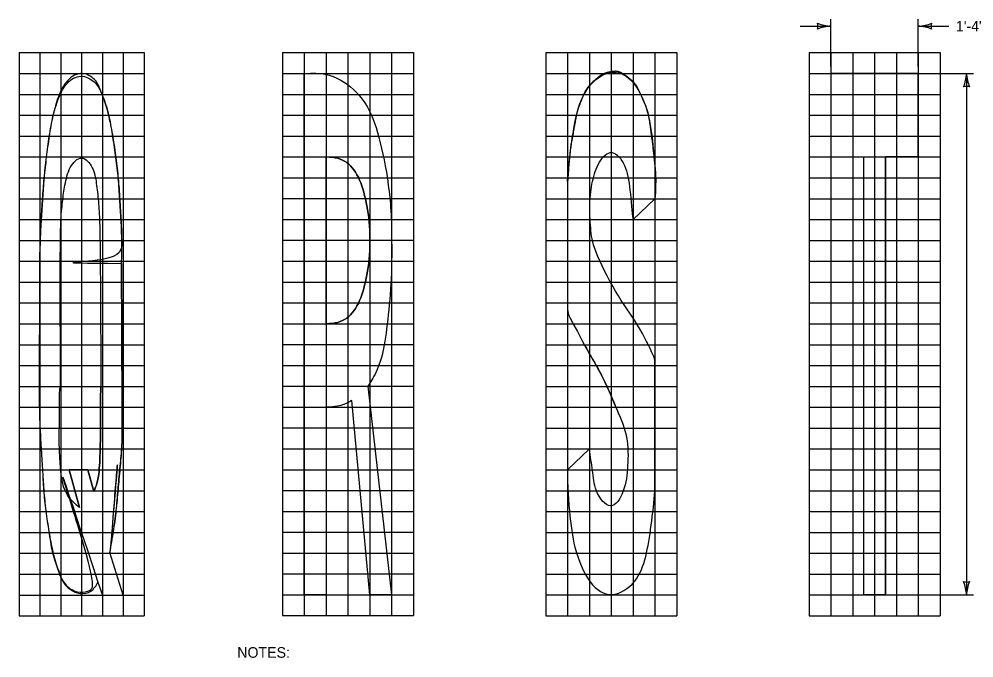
# Model space of a CAD drawing. Extents: x 49991.4 to 50021, y 49987.6 to 50011.4.
# Drawn here: x 50007.25 to 50012.67, y 49991.57 to 49995.18 of the extents above; entities that cross this region are included whole.
import ezdxf

# ---------------------------------------------------------------- set-up
doc = ezdxf.new("R2010")
doc.units = 0
for name, color, linetype in [('Level 1', 7, 'Continuous'), ('Level 2', 7, 'Continuous'), ('Level 3', 7, 'Continuous'), ('Level 9', 7, 'Continuous')]:
    doc.layers.add(name, color=color, linetype=linetype)

msp = doc.modelspace()

# ---------------------------------------------------------------- linework, layer by layer
at = {"layer": 'Level 1'}
for p, q in [((50008.8704, 49991.9224), (50008.8704, 49994.8747)), ((50008.8704, 49991.9224), (50008.8704, 49994.8747)), ((50008.8704, 49991.9224), (50008.8704, 49994.8747)), ((50011.8554, 49994.8747), (50011.8554, 49994.4022)), ((50011.8554, 49994.8747), (50012.3504, 49994.8747)), ((50012.3504, 49994.8747), (50011.8554, 49994.8747)), ((50011.8554, 49994.8747), (50011.8554, 49994.4022)), ((50012.3504, 49994.8747), (50011.8554, 49994.8747)), ((50011.8554, 49994.8747), (50011.8554, 49994.4022)), ((50012.3504, 49994.8747), (50012.3504, 49994.4022)), ((50012.3504, 49994.4022), (50012.3504, 49994.8747)), ((50012.3504, 49994.4022), (50012.3504, 49994.8747)), ((50008.9941, 49993.4576), (50008.9941, 49994.4023)), ((50008.9941, 49994.4023), (50008.9941, 49993.4576)), ((50008.9941, 49994.4023), (50008.9941, 49993.4576)), ((50011.8554, 49994.4022), (50012.041, 49994.4022)), ((50011.8554, 49994.4022), (50012.041, 49994.4022)), ((50011.8554, 49994.4022), (50012.041, 49994.4022)), ((50012.041, 49994.4022), (50012.041, 49991.9215)), ((50012.041, 49994.4022), (50012.041, 49991.9215)), ((50012.041, 49994.4022), (50012.041, 49991.9215)), ((50012.3504, 49994.4022), (50012.1647, 49994.4022)), ((50012.1647, 49994.4022), (50012.1647, 49991.9215)), ((50012.1647, 49991.9215), (50012.1647, 49994.4022)), ((50012.1647, 49994.4022), (50012.3504, 49994.4022)), ((50012.1647, 49991.9215), (50012.1647, 49994.4022)), ((50012.1647, 49994.4022), (50012.3504, 49994.4022)), ((50010.3629, 49994.2641), (50010.3629, 49993.5406)), ((50010.3629, 49994.2641), (50010.3629, 49993.5406)), ((50010.8579, 49994.1659), (50010.7341, 49994.0478)), ((50010.7341, 49994.0478), (50010.8579, 49994.1659)), ((50007.3703, 49992.989), (50007.3716, 49993.8046)), ((50007.835, 49993.7992), (50007.839, 49992.9903)), ((50007.4881, 49993.1994), (50007.4862, 49993.6824)), ((50007.715, 49993.6894), (50007.7173, 49993.1045)), ((50010.8579, 49992.5122), (50010.8579, 49993.2364)), ((50010.8579, 49992.5122), (50010.8579, 49993.2364)), ((50007.4885, 49993.1091), (50007.4881, 49993.1994)), ((50009.23, 49993.1033), (50009.3654, 49991.9224)), ((50009.23, 49993.1033), (50009.3654, 49991.9224)), ((50009.23, 49993.1033), (50009.3654, 49991.9224)), ((50009.2416, 49991.9224), (50009.1397, 49993.0224)), ((50009.2416, 49991.9224), (50009.1397, 49993.0224)), ((50009.2416, 49991.9224), (50009.1397, 49993.0224)), ((50008.9941, 49992.9853), (50008.9941, 49991.9224)), ((50008.9941, 49992.9853), (50008.9941, 49991.9224)), ((50008.9941, 49992.9853), (50008.9941, 49991.9224)), ((50010.3629, 49992.6303), (50010.4866, 49992.7484)), ((50010.4866, 49992.7484), (50010.3629, 49992.6303)), ((50007.537, 49992.6306), (50007.6446, 49992.6306)), ((50007.5969, 49992.4179), (50007.537, 49992.6306)), ((50007.6446, 49992.6306), (50007.678, 49992.5081)), ((50007.8447, 49991.9214), (50007.7693, 49992.1614)), ((50007.701, 49991.994), (50007.7266, 49991.9214)), ((50007.7266, 49991.9214), (50007.8447, 49991.9214)), ((50008.9941, 49991.9224), (50008.8704, 49991.9224)), ((50008.9941, 49991.9224), (50008.8704, 49991.9224)), ((50008.9941, 49991.9224), (50008.8704, 49991.9224)), ((50009.3654, 49991.9224), (50009.2416, 49991.9224)), ((50009.3654, 49991.9224), (50009.2416, 49991.9224)), ((50009.3654, 49991.9224), (50009.2416, 49991.9224)), ((50012.1647, 49991.9215), (50012.041, 49991.9215)), ((50012.041, 49991.9215), (50012.1647, 49991.9215)), ((50012.041, 49991.9215), (50012.1647, 49991.9215))]:
    msp.add_line(p, q, dxfattribs=at)
for points in [[(50007.3716, 49993.8046), (50007.3703, 49992.989)], [(50007.839, 49992.9903), (50007.835, 49993.7992)], [(50007.4885, 49993.1091), (50007.4881, 49993.1994), (50007.4862, 49993.6824)], [(50007.715, 49993.6894), (50007.7173, 49993.1045)], [(50007.537, 49992.6306), (50007.5969, 49992.4179)], [(50007.678, 49992.5081), (50007.6446, 49992.6306), (50007.537, 49992.6306)], [(50007.8447, 49991.9214), (50007.7693, 49992.1614)], [(50007.701, 49991.994), (50007.7266, 49991.9214), (50007.8447, 49991.9214)]]:
    msp.add_lwpolyline(points, dxfattribs=at)
for centre, start, end in [((50010.4629, 49993.5406), 180, 208.2065), ((50010.4629, 49993.5406), 180, 208.2065), ((50010.7579, 49993.2364), 360, 27.9161), ((50010.7579, 49993.2364), 0.0009, 27.9162)]:
    msp.add_arc(centre, 0.1, start, end, dxfattribs=at)
for points, degree in [([(50007.835, 49993.7992), (50007.8358, 49993.8389), (50007.8372, 49993.9113), (50007.8338, 49994.0287), (50007.8259, 49994.1447), (50007.8184, 49994.2663), (50007.806, 49994.3829), (50007.7884, 49994.4994), (50007.7697, 49994.6188), (50007.7456, 49994.7072), (50007.7154, 49994.7773), (50007.6941, 49994.8419), (50007.6016, 49994.895), (50007.5124, 49994.8288), (50007.4698, 49994.7331), (50007.4408, 49994.6226), (50007.4219, 49994.5044), (50007.4058, 49994.386), (50007.3937, 49994.2685), (50007.3865, 49994.1518), (50007.3778, 49994.0363), (50007.3721, 49993.9202), (50007.3718, 49993.843), (50007.3716, 49993.8046)], 3), ([(50007.3716, 49993.8046), (50007.3729, 49993.9197), (50007.3783, 49994.0362), (50007.3863, 49994.1528), (50007.3944, 49994.2666), (50007.4064, 49994.3858), (50007.4225, 49994.505), (50007.4426, 49994.6215), (50007.4747, 49994.738), (50007.5229, 49994.8277), (50007.6019, 49994.8746), (50007.689, 49994.8304), (50007.7211, 49994.7648), (50007.7332, 49994.7353), (50007.768, 49994.6161), (50007.7881, 49994.5009), (50007.8055, 49994.3804), (50007.8175, 49994.2666), (50007.8256, 49994.1514), (50007.8336, 49994.0162), (50007.8363, 49993.9184), (50007.835, 49993.7992), (50007.3716, 49993.8046), (50007.835, 49993.7992)], 3), ([(50008.8704, 49994.8747), (50008.9676, 49994.8817), (50009.0761, 49994.8552), (50009.2272, 49994.718), (50009.2957, 49994.5267), (50009.3522, 49994.2481), (50009.3667, 49994.0494), (50009.3654, 49993.93)], 3), ([(50008.8704, 49994.8747), (50008.9676, 49994.8817), (50009.0761, 49994.8552), (50009.2272, 49994.718), (50009.2957, 49994.5267), (50009.3522, 49994.2481), (50009.3667, 49994.0494), (50009.3654, 49993.93)], 3), ([(50008.8704, 49994.8747), (50008.9676, 49994.8817), (50009.0761, 49994.8552), (50009.2272, 49994.718), (50009.2957, 49994.5267), (50009.3522, 49994.2481), (50009.3667, 49994.0494), (50009.3654, 49993.93)], 3), ([(50010.3629, 49994.2641), (50010.3736, 49994.419), (50010.4054, 49994.6066), (50010.4242, 49994.6921), (50010.4854, 49994.8224), (50010.61, 49994.9017), (50010.7256, 49994.8563), (50010.8047, 49994.7111), (50010.8404, 49994.5666), (50010.8682, 49994.2519), (50010.8579, 49994.1659)], 3), ([(50010.5214, 49994.8404), (50010.4744, 49994.7991), (50010.4494, 49994.7457), (50010.4341, 49994.7068)], 2), ([(50010.5916, 49994.8807), (50010.5668, 49994.8742), (50010.542, 49994.8585), (50010.5214, 49994.8404)], 2), ([(50010.7096, 49994.8497), (50010.678, 49994.875), (50010.6348, 49994.8919), (50010.5916, 49994.8807)], 2), ([(50010.7812, 49994.7485), (50010.7651, 49994.7839), (50010.7444, 49994.8218), (50010.7096, 49994.8497)], 2), ([(50010.8412, 49994.5093), (50010.8268, 49994.6217), (50010.8123, 49994.6805), (50010.7812, 49994.7485)], 2), ([(50010.4341, 49994.7068), (50010.4188, 49994.6677), (50010.4134, 49994.6431), (50010.405, 49994.5981)], 2), ([(50010.405, 49994.5981), (50010.3926, 49994.5312), (50010.3736, 49994.419), (50010.3629, 49994.2641)], 2), ([(50010.8579, 49994.1659), (50010.8682, 49994.2519), (50010.8547, 49994.404), (50010.8412, 49994.5093)], 2), ([(50008.9941, 49994.4023), (50009.0438, 49994.4022), (50009.1175, 49994.3823), (50009.1897, 49994.2795), (50009.2279, 49994.1296), (50009.2436, 49994.0108), (50009.2416, 49993.93)], 3), ([(50009.2416, 49993.93), (50009.2436, 49994.0108), (50009.2279, 49994.1296), (50009.1897, 49994.2795), (50009.1175, 49994.3823), (50009.0438, 49994.4022), (50008.9941, 49994.4023)], 3), ([(50009.2416, 49993.93), (50009.2436, 49994.0108), (50009.2279, 49994.1296), (50009.1897, 49994.2795), (50009.1175, 49994.3823), (50009.0438, 49994.4022), (50008.9941, 49994.4023)], 3), ([(50010.8462, 49993.2832), (50010.83, 49993.3224), (50010.7652, 49993.452), (50010.6343, 49993.6279), (50010.5054, 49993.8898), (50010.4936, 49993.991), (50010.4851, 49994.1427), (50010.5006, 49994.2637), (50010.5359, 49994.3783), (50010.6146, 49994.4552), (50010.6946, 49994.3608), (50010.7181, 49994.2259), (50010.7272, 49994.0852), (50010.7341, 49994.0478)], 3), ([(50010.8462, 49993.2832), (50010.83, 49993.3224), (50010.7652, 49993.452), (50010.6343, 49993.6279), (50010.5054, 49993.8898), (50010.4936, 49993.991), (50010.4851, 49994.1427), (50010.5006, 49994.2637), (50010.5359, 49994.3783), (50010.6146, 49994.4552), (50010.6946, 49994.3608), (50010.7181, 49994.2259), (50010.7272, 49994.0852), (50010.7341, 49994.0478)], 3), ([(50007.4862, 49993.6824), (50007.4862, 49993.7818), (50007.4885, 49993.8651), (50007.4885, 49994.0361), (50007.5002, 49994.1539), (50007.5116, 49994.2395), (50007.5364, 49994.3477), (50007.6091, 49994.4216), (50007.6771, 49994.3429), (50007.6923, 49994.2548), (50007.7043, 49994.1516), (50007.7114, 49994.0363), (50007.7131, 49993.8827), (50007.7143, 49993.7664), (50007.715, 49993.6894)], 3), ([(50007.4862, 49993.6824), (50007.4862, 49993.7818), (50007.4885, 49993.8651), (50007.4885, 49994.0361), (50007.5002, 49994.1539), (50007.5116, 49994.2395), (50007.5364, 49994.3477), (50007.6091, 49994.4216), (50007.6771, 49994.3429), (50007.6923, 49994.2548), (50007.7043, 49994.1516), (50007.7114, 49994.0363), (50007.7131, 49993.8827), (50007.7143, 49993.7664), (50007.715, 49993.6894)], 3), ([(50009.2416, 49993.93), (50009.2436, 49993.8491), (50009.2279, 49993.7304), (50009.1897, 49993.5805), (50009.1175, 49993.4777), (50009.0438, 49993.4578), (50008.9941, 49993.4576)], 3), ([(50008.9941, 49993.4576), (50009.0438, 49993.4578), (50009.1175, 49993.4777), (50009.1897, 49993.5805), (50009.2279, 49993.7304), (50009.2436, 49993.8491), (50009.2416, 49993.93)], 3), ([(50008.9941, 49993.4576), (50009.0438, 49993.4578), (50009.1175, 49993.4777), (50009.1897, 49993.5805), (50009.2279, 49993.7304), (50009.2436, 49993.8491), (50009.2416, 49993.93)], 3), ([(50009.3654, 49993.93), (50009.3674, 49993.8115), (50009.3618, 49993.6537), (50009.3371, 49993.4171), (50009.3111, 49993.2532), (50009.257, 49993.139), (50009.23, 49993.1033), (50009.23, 49993.1033)], 3), ([(50009.3654, 49993.93), (50009.3674, 49993.8115), (50009.3618, 49993.6537), (50009.3371, 49993.4171), (50009.3111, 49993.2532), (50009.257, 49993.139), (50009.23, 49993.1033), (50009.23, 49993.1033)], 3), ([(50009.3654, 49993.93), (50009.3674, 49993.8115), (50009.3618, 49993.6537), (50009.3371, 49993.4171), (50009.3111, 49993.2532), (50009.257, 49993.139), (50009.23, 49993.1033), (50009.23, 49993.1033)], 3), ([(50010.3747, 49993.4933), (50010.4442, 49993.3649), (50010.4819, 49993.2929), (50010.5713, 49993.1446), (50010.6455, 49992.9612), (50010.7081, 49992.8199), (50010.7054, 49992.6479), (50010.6897, 49992.509), (50010.6082, 49992.3829), (50010.5102, 49992.5148), (50010.5082, 49992.6247), (50010.4914, 49992.7076), (50010.4866, 49992.7484)], 3), ([(50010.3747, 49993.4933), (50010.4442, 49993.3649), (50010.4819, 49993.2929), (50010.5358, 49993.2034), (50010.5624, 49993.1506)], 3), ([(50007.5969, 49992.4179), (50007.579, 49992.4306), (50007.5041, 49992.4879), (50007.4869, 49992.6526), (50007.4833, 49992.732), (50007.4797, 49992.8331), (50007.4869, 49992.9667), (50007.4797, 49993.039), (50007.4885, 49993.1091)], 3), ([(50007.5969, 49992.4179), (50007.579, 49992.4306), (50007.5041, 49992.4879), (50007.4869, 49992.6526), (50007.4833, 49992.732), (50007.4797, 49992.8331), (50007.4869, 49992.9667), (50007.4797, 49993.039), (50007.4885, 49993.1091)], 3), ([(50007.678, 49992.5081), (50007.6929, 49992.5426), (50007.7081, 49992.5913), (50007.7145, 49992.7506), (50007.7153, 49992.8672), (50007.7144, 49992.9851), (50007.7163, 49993.0645), (50007.7173, 49993.1045)], 3), ([(50007.7173, 49993.1045), (50007.7163, 49993.0645), (50007.7144, 49992.9851), (50007.7153, 49992.8672), (50007.7145, 49992.7506), (50007.7081, 49992.5913), (50007.6929, 49992.5426), (50007.678, 49992.5081)], 3), ([(50010.5624, 49993.1506), (50010.5956, 49993.0845), (50010.6455, 49992.9612), (50010.7081, 49992.8199), (50010.7054, 49992.6479), (50010.6897, 49992.509), (50010.6082, 49992.3829), (50010.5102, 49992.5148), (50010.5082, 49992.6247), (50010.4914, 49992.7076), (50010.4866, 49992.7484)], 3), ([(50009.1397, 49993.0224), (50009.1397, 49993.0224), (50009.0969, 49992.9976), (50009.0488, 49992.986), (50008.9941, 49992.9853)], 3), ([(50009.1397, 49993.0224), (50009.1397, 49993.0224), (50009.0969, 49992.9976), (50009.0488, 49992.986), (50008.9941, 49992.9853)], 3), ([(50009.1397, 49993.0224), (50009.1397, 49993.0224), (50009.0969, 49992.9976), (50009.0488, 49992.986), (50008.9941, 49992.9853)], 3), ([(50007.3703, 49992.989), (50007.3716, 49992.8725), (50007.3783, 49992.7546), (50007.3863, 49992.6354), (50007.393, 49992.5176), (50007.4051, 49992.3957), (50007.4225, 49992.2819), (50007.4439, 49992.1614), (50007.4774, 49992.0542), (50007.5055, 49991.9913), (50007.5403, 49991.9551), (50007.5993, 49991.931), (50007.6609, 49991.9431), (50007.701, 49991.994), (50007.3703, 49992.989), (50007.701, 49991.994)], 3), ([(50007.3703, 49992.989), (50007.3703, 49992.9501), (50007.3703, 49992.8719), (50007.3782, 49992.7541), (50007.3869, 49992.6359), (50007.3921, 49992.5161), (50007.4033, 49992.3979), (50007.4235, 49992.2797), (50007.4394, 49992.1636), (50007.4724, 49992.0682), (50007.4984, 49991.9943), (50007.5419, 49991.9495), (50007.5972, 49991.9249), (50007.6676, 49991.9355), (50007.6898, 49991.9743), (50007.701, 49991.994)], 3), ([(50007.839, 49992.9903), (50007.839, 49992.8738), (50007.8363, 49992.7533), (50007.8256, 49992.6368), (50007.8149, 49992.5189), (50007.8042, 49992.3984), (50007.7881, 49992.2806), (50007.7693, 49992.1614), (50007.839, 49992.9903), (50007.7693, 49992.1614)], 3), ([(50007.7693, 49992.1614), (50007.7757, 49992.2011), (50007.7883, 49992.2799), (50007.8056, 49992.3989), (50007.8145, 49992.5181), (50007.8251, 49992.6364), (50007.8385, 49992.7543), (50007.8391, 49992.8725), (50007.839, 49992.9515), (50007.839, 49992.9903)], 3), ([(50010.3629, 49992.6303), (50010.3601, 49992.5469), (50010.3758, 49992.3477), (50010.4017, 49992.1716), (50010.484, 49991.9767), (50010.6105, 49991.8938), (50010.7572, 49991.9905), (50010.8096, 49992.1339), (50010.8372, 49992.3119), (50010.8536, 49992.4514), (50010.8579, 49992.5122)], 3), ([(50010.3629, 49992.6303), (50010.3601, 49992.5469), (50010.3758, 49992.3477), (50010.4017, 49992.1716), (50010.484, 49991.9767), (50010.6105, 49991.8938), (50010.7572, 49991.9905), (50010.8096, 49992.1339), (50010.8372, 49992.3119), (50010.8536, 49992.4514), (50010.8579, 49992.5122)], 3)]:
    msp.add_open_spline(points, degree=degree, dxfattribs=at)
at = {"layer": 'Level 3'}
for p, q in [((50011.8554, 49994.9147), (50011.8554, 49995.1828)), ((50012.3504, 49994.9147), (50012.3504, 49995.1828)), ((50011.682, 49995.1428), (50011.8554, 49995.1428)), ((50012.3504, 49995.1428), (50012.5238, 49995.1428)), ((50012.3904, 49994.8747), (50012.6641, 49994.8747)), ((50012.6241, 49994.8747), (50012.6241, 49991.9215)), ((50012.2047, 49991.9215), (50012.6641, 49991.9215))]:
    msp.add_line(p, q, dxfattribs=at)
for centre, radius, start, end in [((50011.8645, 49995.3649), 0.2223, 247.456, 267.6395), ((50011.7271, 49995.1428), 0.0548, 342.1388, 17.8612), ((50011.8669, 49994.9101), 0.233, 92.8273, 112.0772), ((50012.3389, 49995.3755), 0.233, 272.8273, 292.0772), ((50012.3412, 49994.9207), 0.2223, 67.456, 87.6395), ((50012.4786, 49995.1428), 0.0548, 162.1388, 197.8612), ((50012.402, 49994.8838), 0.2223, 337.456, 357.6395), ((50012.8568, 49994.8862), 0.233, 182.8273, 202.0772), ((50012.6241, 49994.7465), 0.0548, 72.1388, 107.8612), ((50012.6241, 49992.0498), 0.0548, 252.1388, 287.8612), ((50012.3914, 49991.91), 0.233, 2.8273, 22.0772), ((50012.8462, 49991.9124), 0.2223, 157.456, 177.6395)]:
    msp.add_arc(centre, radius, start, end, dxfattribs=at)
at = {"layer": 'Level 9'}
for p, q in [((50007.2541, 49994.9928), (50007.2541, 49991.8033)), ((50007.2541, 49994.9928), (50007.9629, 49994.9928)), ((50007.3722, 49994.9928), (50007.3722, 49991.8033)), ((50007.4904, 49994.9928), (50007.4904, 49991.8033)), ((50007.6085, 49994.9928), (50007.6085, 49991.8033)), ((50007.7266, 49994.9928), (50007.7266, 49991.8033)), ((50007.8447, 49994.9928), (50007.8447, 49991.8033)), ((50007.9629, 49994.9928), (50007.9629, 49991.8033)), ((50008.7466, 49994.9928), (50008.7466, 49991.8044)), ((50008.7466, 49994.9928), (50009.4891, 49994.9928)), ((50008.8704, 49994.9928), (50008.8704, 49991.8044)), ((50008.9941, 49994.9928), (50008.9941, 49991.8044)), ((50009.1179, 49994.9928), (50009.1179, 49991.8044)), ((50009.2416, 49994.9928), (50009.2416, 49991.8044)), ((50009.3654, 49994.9928), (50009.3654, 49991.8044)), ((50009.4891, 49994.9928), (50009.4891, 49991.8044)), ((50010.2391, 49994.9928), (50010.9816, 49994.9928)), ((50010.2391, 49994.9928), (50010.2391, 49991.8034)), ((50010.3629, 49994.9928), (50010.3629, 49991.8034)), ((50010.4866, 49994.9928), (50010.4866, 49991.8034)), ((50010.6104, 49994.9928), (50010.6104, 49991.8034)), ((50010.7341, 49994.9928), (50010.7341, 49991.8034)), ((50010.8579, 49994.9928), (50010.8579, 49991.8034)), ((50010.9816, 49994.9928), (50010.9816, 49991.8034)), ((50011.7316, 49994.9928), (50011.7316, 49991.8034)), ((50011.7316, 49994.9928), (50012.4741, 49994.9928)), ((50011.8554, 49994.9928), (50011.8554, 49991.8034)), ((50011.9791, 49994.9928), (50011.9791, 49991.8034)), ((50012.1029, 49994.9928), (50012.1029, 49991.8034)), ((50012.2266, 49994.9928), (50012.2266, 49991.8034)), ((50012.3504, 49994.9928), (50012.3504, 49991.8034)), ((50012.4741, 49994.9928), (50012.4741, 49991.8034)), ((50007.2541, 49994.8747), (50007.9629, 49994.8747)), ((50008.7466, 49994.8747), (50009.4891, 49994.8747)), ((50010.2391, 49994.8747), (50010.9816, 49994.8747)), ((50011.7316, 49994.8747), (50012.4741, 49994.8747)), ((50012.2266, 49994.8747), (50012.2266, 49991.9215)), ((50007.2541, 49994.7565), (50007.9629, 49994.7565)), ((50008.7466, 49994.7566), (50009.4891, 49994.7566)), ((50010.2391, 49994.7565), (50010.9816, 49994.7565)), ((50011.7316, 49994.7565), (50012.4741, 49994.7565)), ((50007.2541, 49994.6384), (50007.9629, 49994.6384)), ((50008.7466, 49994.6385), (50009.4891, 49994.6385)), ((50010.2391, 49994.6384), (50010.9816, 49994.6384)), ((50011.7316, 49994.6384), (50012.4741, 49994.6384)), ((50007.2541, 49994.5203), (50007.9629, 49994.5203)), ((50008.7466, 49994.5204), (50009.4891, 49994.5204)), ((50010.2391, 49994.5203), (50010.9816, 49994.5203)), ((50011.7316, 49994.5203), (50012.4741, 49994.5203)), ((50008.7466, 49994.4023), (50009.4891, 49994.4023)), ((50007.2541, 49994.4021), (50007.9629, 49994.4021)), ((50010.2391, 49994.4022), (50010.9816, 49994.4022)), ((50011.7316, 49994.4022), (50012.4741, 49994.4022)), ((50007.2541, 49994.284), (50007.9629, 49994.284)), ((50008.7466, 49994.2842), (50009.4891, 49994.2842)), ((50010.2391, 49994.284), (50010.9816, 49994.284)), ((50011.7316, 49994.284), (50012.4741, 49994.284)), ((50007.2541, 49994.1659), (50007.9629, 49994.1659)), ((50008.7466, 49994.1662), (50009.4891, 49994.1662)), ((50010.2391, 49994.1659), (50010.9816, 49994.1659)), ((50011.7316, 49994.1659), (50012.4741, 49994.1659)), ((50007.2541, 49994.0477), (50007.9629, 49994.0477)), ((50008.7466, 49994.0481), (50009.4891, 49994.0481)), ((50010.2391, 49994.0478), (50010.9816, 49994.0478)), ((50011.7316, 49994.0478), (50012.4741, 49994.0478)), ((50007.2541, 49993.9296), (50007.9629, 49993.9296)), ((50008.7466, 49993.93), (50009.4891, 49993.93)), ((50010.2391, 49993.9297), (50010.9816, 49993.9297)), ((50011.7316, 49993.9297), (50012.4741, 49993.9297)), ((50007.2541, 49993.8115), (50007.9629, 49993.8115)), ((50008.7466, 49993.8119), (50009.4891, 49993.8119)), ((50010.2391, 49993.8115), (50010.9816, 49993.8115)), ((50011.7316, 49993.8115), (50012.4741, 49993.8115)), ((50007.2541, 49993.6934), (50007.9629, 49993.6934)), ((50008.7466, 49993.6938), (50009.4891, 49993.6938)), ((50010.2391, 49993.6934), (50010.9816, 49993.6934)), ((50011.7316, 49993.6934), (50012.4741, 49993.6934)), ((50007.2541, 49993.5752), (50007.9629, 49993.5752)), ((50008.7466, 49993.5757), (50009.4891, 49993.5757)), ((50010.2391, 49993.5753), (50010.9816, 49993.5753)), ((50011.7316, 49993.5753), (50012.4741, 49993.5753)), ((50007.2541, 49993.4571), (50007.9629, 49993.4571)), ((50008.7466, 49993.4576), (50009.4891, 49993.4576)), ((50010.2391, 49993.4572), (50010.9816, 49993.4572)), ((50011.7316, 49993.4572), (50012.4741, 49993.4572)), ((50007.2541, 49993.339), (50007.9629, 49993.339)), ((50008.7466, 49993.3395), (50009.4891, 49993.3395)), ((50010.2391, 49993.339), (50010.9816, 49993.339)), ((50011.7316, 49993.339), (50012.4741, 49993.339)), ((50007.2541, 49993.2208), (50007.9629, 49993.2208)), ((50008.7466, 49993.2214), (50009.4891, 49993.2214)), ((50010.2391, 49993.2209), (50010.9816, 49993.2209)), ((50011.7316, 49993.2209), (50012.4741, 49993.2209)), ((50007.2541, 49993.1027), (50007.9629, 49993.1027)), ((50008.7466, 49993.1033), (50009.4891, 49993.1033)), ((50010.2391, 49993.1028), (50010.9816, 49993.1028)), ((50011.7316, 49993.1028), (50012.4741, 49993.1028)), ((50007.2541, 49992.9846), (50007.9629, 49992.9846)), ((50008.7466, 49992.9853), (50009.4891, 49992.9853)), ((50010.2391, 49992.9847), (50010.9816, 49992.9847)), ((50011.7316, 49992.9847), (50012.4741, 49992.9847)), ((50007.2541, 49992.8664), (50007.9629, 49992.8664)), ((50008.7466, 49992.8672), (50009.4891, 49992.8672)), ((50010.2391, 49992.8665), (50010.9816, 49992.8665)), ((50011.7316, 49992.8665), (50012.4741, 49992.8665)), ((50007.2541, 49992.7483), (50007.9629, 49992.7483)), ((50008.7466, 49992.7491), (50009.4891, 49992.7491)), ((50010.2391, 49992.7484), (50010.9816, 49992.7484)), ((50011.7316, 49992.7484), (50012.4741, 49992.7484)), ((50007.2541, 49992.6302), (50007.9629, 49992.6302)), ((50008.7466, 49992.631), (50009.4891, 49992.631)), ((50010.2391, 49992.6303), (50010.9816, 49992.6303)), ((50011.7316, 49992.6303), (50012.4741, 49992.6303)), ((50007.2541, 49992.512), (50007.9629, 49992.512)), ((50008.7466, 49992.5129), (50009.4891, 49992.5129)), ((50010.2391, 49992.5122), (50010.9816, 49992.5122)), ((50011.7316, 49992.5122), (50012.4741, 49992.5122)), ((50007.2541, 49992.3939), (50007.9629, 49992.3939)), ((50008.7466, 49992.3948), (50009.4891, 49992.3948)), ((50010.2391, 49992.394), (50010.9816, 49992.394)), ((50011.7316, 49992.394), (50012.4741, 49992.394)), ((50007.2541, 49992.2758), (50007.9629, 49992.2758)), ((50008.7466, 49992.2767), (50009.4891, 49992.2767)), ((50010.2391, 49992.2759), (50010.9816, 49992.2759)), ((50011.7316, 49992.2759), (50012.4741, 49992.2759)), ((50007.2541, 49992.1576), (50007.9629, 49992.1576)), ((50008.7466, 49992.1586), (50009.4891, 49992.1586)), ((50010.2391, 49992.1578), (50010.9816, 49992.1578)), ((50011.7316, 49992.1578), (50012.4741, 49992.1578)), ((50007.2541, 49992.0395), (50007.9629, 49992.0395)), ((50008.7466, 49992.0405), (50009.4891, 49992.0405)), ((50010.2391, 49992.0397), (50010.9816, 49992.0397)), ((50011.7316, 49992.0397), (50012.4741, 49992.0397)), ((50007.2541, 49991.9214), (50007.9629, 49991.9214)), ((50008.7466, 49991.9224), (50009.4891, 49991.9224)), ((50010.2391, 49991.9215), (50010.9816, 49991.9215)), ((50011.7316, 49991.9215), (50012.4741, 49991.9215)), ((50007.2541, 49991.8033), (50007.9629, 49991.8033)), ((50008.7466, 49991.8044), (50009.4891, 49991.8044)), ((50010.2391, 49991.8034), (50010.9816, 49991.8034)), ((50011.7316, 49991.8034), (50012.4741, 49991.8034))]:
    msp.add_line(p, q, dxfattribs=at)

# ---------------------------------------------------------------- texts
at = {"layer": 'Level 2'}
for s, p in [('1\'-4" [400] (TYP. LETTER WIDTH)', (50012.5638, 49995.1128)), ('NOTES:', (50008.4907, 49991.5661))]:
    msp.add_text(s, height=0.06, dxfattribs=at).set_placement(p)

doc.saveas('drawing.dxf')
